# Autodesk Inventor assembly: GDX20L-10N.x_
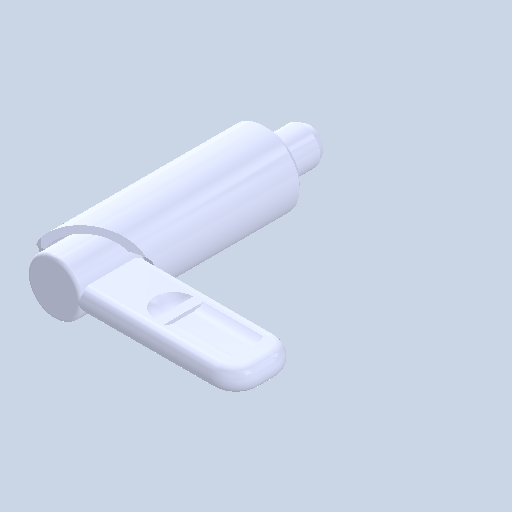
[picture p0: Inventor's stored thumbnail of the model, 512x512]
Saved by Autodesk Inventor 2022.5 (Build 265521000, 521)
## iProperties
Created: 2024-06
Part Number: GDX20L-10N.x_
Document SubType Name: Assembly
Designer: ImaoCorp
Author: ImaoCorp
Sending System: SOLIDWORKS 2022-2022290
MC: AMD64
MC_MODEL: Intel64 Family 6 Model 60 Stepping 3, GenuineIntel
OS: Windows_NT
FRU: Parasolid Version 33.1, build 260,  4-25-2022
FORMAT: text
GUISE: transmit
KEY: FILEGDX20L-10N.x_t
DATE: Wed Jun 12 09:32:43 2024
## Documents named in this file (3)
- Y:\5.更新分\2024年対応\xxxx_GDX\データ_imao品番\gdx20l-10n\GDX20L-10N.x_.iam
- Y:\5.更新分\2024年対応\xxxx_GDX\データ_imao品番\gdx20l-10n\GDX20L-10N_01.ipt
- Y:\5.更新分\2024年対応\xxxx_GDX\データ_imao品番\gdx20l-10n\GDX20L-10N_02.ipt
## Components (2 placed, 2 different names)
1. GDX20L-10N_01
2. GDX20L-10N_02
